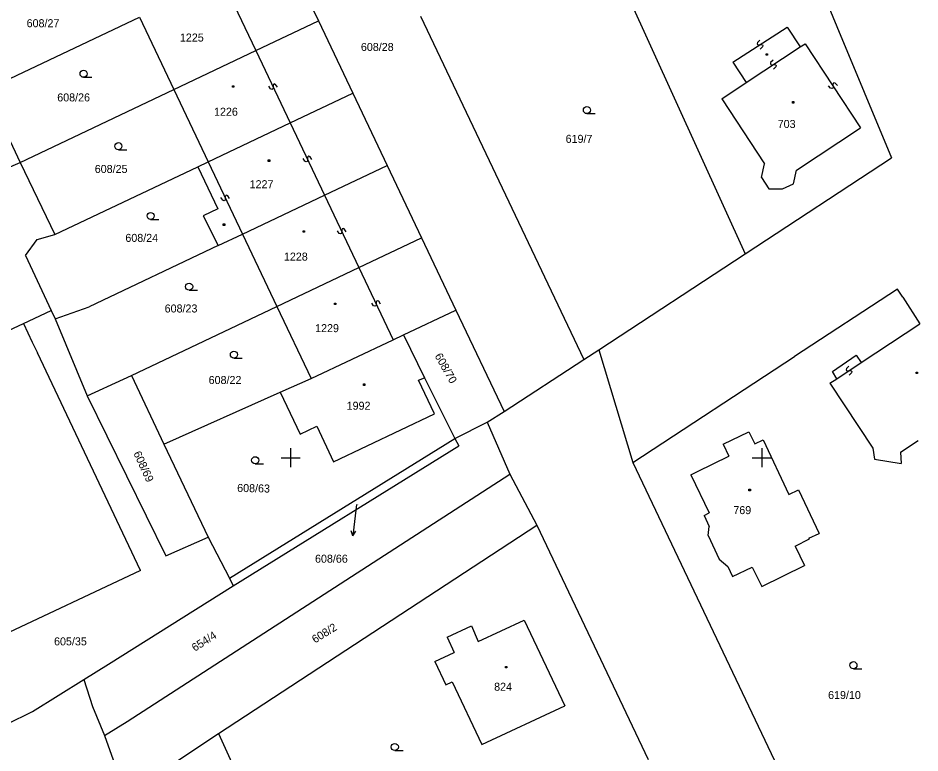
# Model space of a CAD drawing. Extents: x -493648 to -493033, y -1127718 to -1127026.
# Drawn here: x -493128.9 to -493033.2, y -1127181.4 to -1127103.3 of the extents above; entities that cross this region are included whole.
import ezdxf

# ---------------------------------------------------------------- set-up
doc = ezdxf.new("R2010")
doc.units = 0
doc.layers.add('katastrální mapa', color=7, linetype='Continuous')
doc.layers.add('síť', color=7, linetype='Continuous')

msp = doc.modelspace()

# ---------------------------------------------------------------- linework, layer by layer
at = {"layer": 'katastrální mapa'}
for p, q in [((-493067.27, -1127094.16), (-493051.77, -1127128.35)), ((-493100.69, -1127095.92), (-493097.05, -1127103.6)), ((-493045.2, -1127096.54), (-493042.01, -1127104.2)), ((-493107.33, -1127099.07), (-493103.69, -1127106.75)), ((-493132.35, -1127110.95), (-493116.05, -1127103.21)), ((-493116.05, -1127103.21), (-493112.4, -1127110.89)), ((-493086.2, -1127103.11), (-493068.87, -1127139.58)), ((-493103.69, -1127106.75), (-493097.05, -1127103.6)), ((-493097.05, -1127103.6), (-493093.4, -1127111.28)), ((-493042.01, -1127104.2), (-493036.22, -1127118.15)), ((-493053.06, -1127107.97), (-493047.3, -1127104.27)), ((-493047.3, -1127104.27), (-493045.91, -1127106.37)), ((-493050.45, -1127105.88), (-493050.48, -1127106.02)), ((-493050.48, -1127106.02), (-493050.43, -1127106.1)), ((-493050.19, -1127105.65), (-493050.45, -1127105.88)), ((-493050.43, -1127106.1), (-493050.29, -1127106.13)), ((-493050.29, -1127106.13), (-493050.07, -1127106.11)), ((-493050.07, -1127106.11), (-493049.93, -1127106.14)), ((-493049.93, -1127106.14), (-493049.88, -1127106.22)), ((-493045.91, -1127106.37), (-493045.39, -1127106.02)), ((-493045.39, -1127106.02), (-493039.5, -1127114.94)), ((-493112.4, -1127110.89), (-493103.69, -1127106.75)), ((-493103.69, -1127106.75), (-493100.04, -1127114.43)), ((-493051.63, -1127110.14), (-493045.91, -1127106.37)), ((-493049.91, -1127106.36), (-493050.17, -1127106.59)), ((-493049.88, -1127106.22), (-493049.91, -1127106.36)), ((-493049.53, -1127107.1), (-493049.38, -1127107.1)), ((-493049.53, -1127107.25), (-493049.53, -1127107.1)), ((-493049.38, -1127107.1), (-493049.38, -1127107.25)), ((-493053.06, -1127107.97), (-493051.63, -1127110.14)), ((-493049.38, -1127107.25), (-493049.53, -1127107.25)), ((-493049.05, -1127108.02), (-493049.07, -1127108.16)), ((-493048.78, -1127107.78), (-493049.05, -1127108.02)), ((-493049.07, -1127108.16), (-493049.02, -1127108.24)), ((-493049.02, -1127108.24), (-493048.88, -1127108.27)), ((-493048.88, -1127108.27), (-493048.66, -1127108.24)), ((-493048.49, -1127108.49), (-493048.76, -1127108.73)), ((-493048.66, -1127108.24), (-493048.52, -1127108.27)), ((-493048.52, -1127108.27), (-493048.47, -1127108.35)), ((-493048.47, -1127108.35), (-493048.49, -1127108.49)), ((-493121.98, -1127109.59), (-493121.1, -1127109.59)), ((-493128.69, -1127118.63), (-493112.4, -1127110.89)), ((-493112.4, -1127110.89), (-493108.76, -1127118.57)), ((-493106.17, -1127110.49), (-493106.02, -1127110.49)), ((-493106.17, -1127110.64), (-493106.17, -1127110.49)), ((-493106.02, -1127110.64), (-493106.17, -1127110.64)), ((-493106.02, -1127110.49), (-493106.02, -1127110.64)), ((-493102.14, -1127110.83), (-493102.33, -1127110.54)), ((-493102, -1127110.88), (-493102.14, -1127110.83)), ((-493101.91, -1127110.84), (-493102, -1127110.88)), ((-493101.87, -1127110.7), (-493101.91, -1127110.84)), ((-493101.86, -1127110.48), (-493101.87, -1127110.7)), ((-493101.82, -1127110.34), (-493101.86, -1127110.48)), ((-493101.73, -1127110.3), (-493101.82, -1127110.34)), ((-493101.59, -1127110.35), (-493101.73, -1127110.3)), ((-493101.4, -1127110.64), (-493101.59, -1127110.35)), ((-493054.24, -1127111.87), (-493051.63, -1127110.14)), ((-493042.68, -1127110.76), (-493042.92, -1127110.49)), ((-493042.54, -1127110.78), (-493042.68, -1127110.76)), ((-493042.46, -1127110.73), (-493042.54, -1127110.78)), ((-493042.43, -1127110.23), (-493042.46, -1127110.37)), ((-493042.46, -1127110.37), (-493042.43, -1127110.59)), ((-493042.43, -1127110.59), (-493042.46, -1127110.73)), ((-493042.35, -1127110.18), (-493042.43, -1127110.23)), ((-493042.21, -1127110.2), (-493042.35, -1127110.18)), ((-493041.97, -1127110.47), (-493042.21, -1127110.2)), ((-493132.35, -1127110.95), (-493128.69, -1127118.63)), ((-493100.04, -1127114.43), (-493093.4, -1127111.28)), ((-493093.4, -1127111.28), (-493089.75, -1127118.95)), ((-493054.24, -1127111.87), (-493049.69, -1127118.77)), ((-493046.72, -1127112.17), (-493046.57, -1127112.17)), ((-493046.72, -1127112.32), (-493046.72, -1127112.17)), ((-493046.57, -1127112.32), (-493046.72, -1127112.32)), ((-493046.57, -1127112.17), (-493046.57, -1127112.32)), ((-493068.55, -1127113.45), (-493067.67, -1127113.45)), ((-493108.76, -1127118.57), (-493100.04, -1127114.43)), ((-493100.04, -1127114.43), (-493096.39, -1127122.11)), ((-493046.32, -1127119.47), (-493039.5, -1127114.94)), ((-493118.28, -1127117.28), (-493117.4, -1127117.28)), ((-493109.86, -1127119.09), (-493108.76, -1127118.57)), ((-493108.76, -1127118.57), (-493105.11, -1127126.25)), ((-493102.37, -1127118.37), (-493102.22, -1127118.37)), ((-493102.37, -1127118.52), (-493102.37, -1127118.37)), ((-493102.22, -1127118.52), (-493102.37, -1127118.52)), ((-493102.22, -1127118.37), (-493102.22, -1127118.52)), ((-493098.49, -1127118.51), (-493098.68, -1127118.22)), ((-493098.35, -1127118.56), (-493098.49, -1127118.51)), ((-493098.26, -1127118.52), (-493098.35, -1127118.56)), ((-493098.22, -1127118.38), (-493098.26, -1127118.52)), ((-493098.21, -1127118.16), (-493098.22, -1127118.38)), ((-493098.17, -1127118.02), (-493098.21, -1127118.16)), ((-493098.08, -1127117.98), (-493098.17, -1127118.02)), ((-493097.94, -1127118.03), (-493098.08, -1127117.98)), ((-493097.75, -1127118.32), (-493097.94, -1127118.03)), ((-493051.77, -1127128.35), (-493036.22, -1127118.15)), ((-493130.25, -1127119.31), (-493128.69, -1127118.63)), ((-493128.69, -1127118.63), (-493125.04, -1127126.3)), ((-493125.04, -1127126.3), (-493109.86, -1127119.09)), ((-493109.86, -1127119.09), (-493107.74, -1127123.56)), ((-493096.39, -1127122.11), (-493089.75, -1127118.95)), ((-493089.75, -1127118.95), (-493086.11, -1127126.63)), ((-493050.03, -1127120.23), (-493049.69, -1127118.77)), ((-493046.64, -1127120.91), (-493046.32, -1127119.47)), ((-493050.03, -1127120.23), (-493049.24, -1127121.43)), ((-493049.24, -1127121.43), (-493047.8, -1127121.43)), ((-493047.8, -1127121.43), (-493046.64, -1127120.91)), ((-493107.21, -1127122.65), (-493107.4, -1127122.36)), ((-493106.93, -1127122.3), (-493106.94, -1127122.52)), ((-493106.89, -1127122.16), (-493106.93, -1127122.3)), ((-493106.8, -1127122.12), (-493106.89, -1127122.16)), ((-493106.66, -1127122.17), (-493106.8, -1127122.12)), ((-493106.47, -1127122.46), (-493106.66, -1127122.17)), ((-493105.11, -1127126.25), (-493096.39, -1127122.11)), ((-493096.39, -1127122.11), (-493092.75, -1127129.78)), ((-493107.07, -1127122.7), (-493107.21, -1127122.65)), ((-493106.98, -1127122.66), (-493107.07, -1127122.7)), ((-493106.94, -1127122.52), (-493106.98, -1127122.66)), ((-493107.74, -1127123.56), (-493109.3, -1127124.3)), ((-493109.3, -1127124.3), (-493107.68, -1127127.47)), ((-493114.86, -1127124.69), (-493113.98, -1127124.69)), ((-493107.15, -1127125.17), (-493107, -1127125.17)), ((-493107.15, -1127125.32), (-493107.15, -1127125.17)), ((-493107, -1127125.17), (-493107, -1127125.32)), ((-493107.68, -1127127.47), (-493105.11, -1127126.25)), ((-493107, -1127125.32), (-493107.15, -1127125.32)), ((-493105.11, -1127126.25), (-493101.47, -1127133.92)), ((-493098.66, -1127125.88), (-493098.51, -1127125.88)), ((-493098.66, -1127126.03), (-493098.66, -1127125.88)), ((-493098.51, -1127126.03), (-493098.66, -1127126.03)), ((-493098.51, -1127125.88), (-493098.51, -1127126.03)), ((-493094.84, -1127126.19), (-493095.04, -1127125.89)), ((-493094.71, -1127126.23), (-493094.84, -1127126.19)), ((-493094.62, -1127126.19), (-493094.71, -1127126.23)), ((-493094.57, -1127126.06), (-493094.62, -1127126.19)), ((-493094.52, -1127125.7), (-493094.57, -1127125.83)), ((-493094.57, -1127125.83), (-493094.57, -1127126.06)), ((-493094.43, -1127125.66), (-493094.52, -1127125.7)), ((-493094.3, -1127125.7), (-493094.43, -1127125.66)), ((-493094.1, -1127126), (-493094.3, -1127125.7)), ((-493128.13, -1127128.52), (-493126.91, -1127126.81)), ((-493126.91, -1127126.81), (-493125.04, -1127126.3)), ((-493092.75, -1127129.78), (-493086.11, -1127126.63)), ((-493086.11, -1127126.63), (-493082.46, -1127134.31)), ((-493107.68, -1127127.47), (-493121.38, -1127133.98)), ((-493128.13, -1127128.52), (-493125.41, -1127134.36)), ((-493067.3, -1127138.55), (-493051.77, -1127128.35)), ((-493101.47, -1127133.92), (-493092.75, -1127129.78)), ((-493092.75, -1127129.78), (-493089.1, -1127137.46)), ((-493110.77, -1127132.2), (-493109.89, -1127132.2)), ((-493035.59, -1127132.09), (-493046.51, -1127139.25)), ((-493035.02, -1127132.96), (-493035.59, -1127132.09)), ((-493095.34, -1127133.57), (-493095.19, -1127133.57)), ((-493095.34, -1127133.72), (-493095.34, -1127133.57)), ((-493095.19, -1127133.72), (-493095.34, -1127133.72)), ((-493095.19, -1127133.57), (-493095.19, -1127133.72)), ((-493091.2, -1127133.86), (-493091.39, -1127133.57)), ((-493091.06, -1127133.91), (-493091.2, -1127133.86)), ((-493090.97, -1127133.87), (-493091.06, -1127133.91)), ((-493090.93, -1127133.73), (-493090.97, -1127133.87)), ((-493090.92, -1127133.51), (-493090.93, -1127133.73)), ((-493090.88, -1127133.37), (-493090.92, -1127133.51)), ((-493090.79, -1127133.33), (-493090.88, -1127133.37)), ((-493090.65, -1127133.38), (-493090.79, -1127133.33)), ((-493090.46, -1127133.67), (-493090.65, -1127133.38)), ((-493035.02, -1127132.96), (-493033.2, -1127135.76)), ((-493128.35, -1127135.75), (-493125.41, -1127134.36)), ((-493125.41, -1127134.36), (-493125, -1127135.23)), ((-493125, -1127135.23), (-493121.38, -1127133.98)), ((-493116.9, -1127141.26), (-493101.47, -1127133.92)), ((-493101.47, -1127133.92), (-493097.82, -1127141.6)), ((-493088.02, -1127136.95), (-493082.46, -1127134.31)), ((-493082.46, -1127134.31), (-493077.35, -1127145.08)), ((-493130.46, -1127136.74), (-493128.35, -1127135.75)), ((-493128.35, -1127135.75), (-493127.42, -1127137.73)), ((-493125, -1127135.23), (-493121.58, -1127143.43)), ((-493039.44, -1127139.89), (-493033.2, -1127135.76)), ((-493127.42, -1127137.73), (-493126.88, -1127138.86)), ((-493097.82, -1127141.6), (-493089.1, -1127137.46)), ((-493089.1, -1127137.46), (-493088.02, -1127136.95)), ((-493088.02, -1127136.95), (-493085.79, -1127141.51)), ((-493068.87, -1127139.58), (-493067.3, -1127138.55)), ((-493067.3, -1127138.55), (-493063.68, -1127150.51)), ((-493115.95, -1127161.97), (-493126.88, -1127138.86)), ((-493106.02, -1127139.42), (-493105.14, -1127139.42)), ((-493077.35, -1127145.08), (-493068.87, -1127139.58)), ((-493063.68, -1127150.51), (-493046.51, -1127139.25)), ((-493042.5, -1127140.85), (-493039.96, -1127139.12)), ((-493039.96, -1127139.12), (-493039.44, -1127139.89)), ((-493042.03, -1127141.61), (-493039.44, -1127139.89)), ((-493041.01, -1127140.51), (-493041.04, -1127140.65)), ((-493040.75, -1127140.28), (-493041.01, -1127140.51)), ((-493117.73, -1127141.65), (-493116.9, -1127141.26)), ((-493116.9, -1127141.26), (-493113.44, -1127148.57)), ((-493085.79, -1127141.51), (-493082.56, -1127147.94)), ((-493042.03, -1127141.61), (-493042.5, -1127140.85)), ((-493041.04, -1127140.65), (-493040.98, -1127140.74)), ((-493040.98, -1127140.74), (-493040.85, -1127140.76)), ((-493040.85, -1127140.76), (-493040.62, -1127140.74)), ((-493040.46, -1127140.99), (-493040.72, -1127141.22)), ((-493040.62, -1127140.74), (-493040.49, -1127140.76)), ((-493040.49, -1127140.76), (-493040.43, -1127140.85)), ((-493040.43, -1127140.85), (-493040.46, -1127140.99)), ((-493033.6, -1127140.9), (-493033.45, -1127140.9)), ((-493033.6, -1127141.05), (-493033.6, -1127140.9)), ((-493033.45, -1127141.05), (-493033.6, -1127141.05)), ((-493033.45, -1127140.9), (-493033.45, -1127141.05)), ((-493121.58, -1127143.43), (-493117.73, -1127141.65)), ((-493101.11, -1127143.03), (-493097.82, -1127141.6)), ((-493092.27, -1127142.16), (-493092.12, -1127142.16)), ((-493092.27, -1127142.31), (-493092.27, -1127142.16)), ((-493092.12, -1127142.31), (-493092.27, -1127142.31)), ((-493092.12, -1127142.16), (-493092.12, -1127142.31)), ((-493042.76, -1127142.09), (-493042.03, -1127141.61)), ((-493042.76, -1127142.09), (-493038.2, -1127148.97)), ((-493121.58, -1127143.43), (-493113.24, -1127160.42)), ((-493113.44, -1127148.57), (-493101.11, -1127143.03)), ((-493079.13, -1127146.23), (-493077.35, -1127145.08)), ((-493082.56, -1127147.94), (-493079.13, -1127146.23)), ((-493079.13, -1127146.23), (-493076.73, -1127151.76)), ((-493054.1, -1127148.57), (-493051.35, -1127147.24)), ((-493051.35, -1127147.24), (-493050.73, -1127148.51)), ((-493106.5, -1127162.8), (-493082.56, -1127147.94)), ((-493082.56, -1127147.94), (-493082.16, -1127148.75)), ((-493050.73, -1127148.51), (-493049.83, -1127148.09)), ((-493049.83, -1127148.09), (-493047.13, -1127153.9)), ((-493035.25, -1127149.39), (-493033.38, -1127148.17)), ((-493113.44, -1127148.57), (-493108.75, -1127158.45)), ((-493106.09, -1127163.6), (-493082.16, -1127148.75)), ((-493054.1, -1127148.57), (-493053.48, -1127149.85)), ((-493038.2, -1127148.97), (-493038.02, -1127150.15)), ((-493038.02, -1127150.15), (-493035.21, -1127150.61)), ((-493035.25, -1127149.39), (-493035.21, -1127150.61)), ((-493103.76, -1127150.64), (-493102.88, -1127150.64)), ((-493063.68, -1127150.51), (-493043.37, -1127193.26)), ((-493117.34, -1127178.03), (-493076.73, -1127151.76)), ((-493076.73, -1127151.76), (-493073.86, -1127157.16)), ((-493057.53, -1127151.81), (-493055.57, -1127155.86)), ((-493051.35, -1127153.35), (-493051.2, -1127153.35)), ((-493051.35, -1127153.5), (-493051.35, -1127153.35)), ((-493051.2, -1127153.5), (-493051.35, -1127153.5)), ((-493051.2, -1127153.35), (-493051.2, -1127153.5)), ((-493047.13, -1127153.9), (-493046.09, -1127153.41)), ((-493046.09, -1127153.41), (-493043.89, -1127158.04)), ((-493093.01, -1127154.96), (-493093.22, -1127156.79)), ((-493056.11, -1127156.12), (-493055.57, -1127155.86)), ((-493093.22, -1127156.79), (-493093.39, -1127158.28)), ((-493056.11, -1127156.12), (-493055.56, -1127157.3)), ((-493107.66, -1127179.29), (-493073.86, -1127157.16)), ((-493093.39, -1127158.28), (-493093.58, -1127157.76)), ((-493093.39, -1127158.28), (-493093.09, -1127157.81)), ((-493073.86, -1127157.16), (-493062.04, -1127182.05)), ((-493055.67, -1127158.26), (-493055.56, -1127157.3)), ((-493113.24, -1127160.42), (-493108.75, -1127158.45)), ((-493108.75, -1127158.45), (-493106.5, -1127162.8)), ((-493055.67, -1127158.26), (-493054.51, -1127160.76)), ((-493046.46, -1127159.38), (-493044.94, -1127158.63)), ((-493044.98, -1127158.54), (-493043.89, -1127158.04)), ((-493044.98, -1127158.54), (-493044.94, -1127158.63)), ((-493046.46, -1127159.38), (-493045.45, -1127161.45)), ((-493054.51, -1127160.76), (-493053.59, -1127161.54)), ((-493053.59, -1127161.54), (-493053.09, -1127162.63)), ((-493053.09, -1127162.63), (-493051, -1127161.61)), ((-493051, -1127161.61), (-493049.98, -1127163.67)), ((-493049.98, -1127163.67), (-493045.45, -1127161.45)), ((-493115.95, -1127161.97), (-493133.58, -1127170.28)), ((-493106.5, -1127162.8), (-493106.09, -1127163.6)), ((-493119.32, -1127171.94), (-493106.09, -1127163.6)), ((-493080.09, -1127169.51), (-493075.21, -1127167.24)), ((-493075.21, -1127167.24), (-493070.9, -1127176.36)), ((-493083.39, -1127169.07), (-493080.81, -1127167.86)), ((-493080.81, -1127167.86), (-493080.09, -1127169.51)), ((-493083.39, -1127169.07), (-493082.63, -1127170.67)), ((-493084.68, -1127171.63), (-493082.63, -1127170.67)), ((-493121.95, -1127173.57), (-493119.32, -1127171.94)), ((-493084.68, -1127171.63), (-493083.52, -1127174.12)), ((-493077.2, -1127172.18), (-493077.05, -1127172.18)), ((-493077.2, -1127172.33), (-493077.2, -1127172.18)), ((-493077.05, -1127172.18), (-493077.05, -1127172.33)), ((-493077.05, -1127172.33), (-493077.2, -1127172.33)), ((-493040.26, -1127172.41), (-493039.38, -1127172.41)), ((-493127.41, -1127176.97), (-493121.95, -1127173.57)), ((-493121.95, -1127173.57), (-493121.04, -1127176.44)), ((-493083.52, -1127174.12), (-493082.84, -1127173.8)), ((-493082.84, -1127173.8), (-493079.72, -1127180.47)), ((-493130.11, -1127178.29), (-493127.41, -1127176.97)), ((-493121.04, -1127176.44), (-493119.75, -1127179.52)), ((-493079.72, -1127180.47), (-493070.9, -1127176.36)), ((-493119.75, -1127179.52), (-493117.34, -1127178.03)), ((-493119.75, -1127179.52), (-493117.52, -1127185.82)), ((-493117.52, -1127185.82), (-493107.66, -1127179.29)), ((-493107.66, -1127179.29), (-493098.45, -1127199.56)), ((-493088.94, -1127181.1), (-493088.06, -1127181.1))]:
    msp.add_line(p, q, dxfattribs=at)
for points in [[(-493101.11, -1127143.03), (-493098.99, -1127147.5), (-493097.23, -1127146.66), (-493095.44, -1127150.42), (-493084.72, -1127145.35), (-493086.42, -1127141.77), (-493085.79, -1127141.51)], [(-493057.53, -1127151.81), (-493056.81, -1127151.46), (-493053.48, -1127149.85)]]:
    msp.add_lwpolyline(points, dxfattribs=at)
for centre in [(-493121.98, -1127109.215), (-493068.55, -1127113.075), (-493118.28, -1127116.905), (-493114.86, -1127124.315), (-493110.77, -1127131.825), (-493106.02, -1127139.045), (-493103.76, -1127150.265), (-493040.26, -1127172.035), (-493088.94, -1127180.725)]:
    msp.add_circle(centre, 0.375, dxfattribs=at)
at = {"layer": 'síť'}
for p, q in [((-493100, -1127149), (-493100, -1127151)), ((-493050, -1127149), (-493050, -1127151)), ((-493101, -1127150), (-493099, -1127150)), ((-493051, -1127150), (-493049, -1127150))]:
    msp.add_line(p, q, dxfattribs=at)

# ---------------------------------------------------------------- texts
at = {"layer": 'katastrální mapa'}
for s, height, p in [('608/27', 0.849996, (-493128.02, -1127104.27)), ('1225', 0.849996, (-493111.75, -1127105.79)), ('608/28', 0.849996, (-493092.54, -1127106.79)), ('608/26', 0.849996, (-493124.77, -1127112.15)), ('1226', 0.849996, (-493108.13, -1127113.67)), ('703', 0.849996, (-493048.3, -1127114.97)), ('619/7', 0.849996, (-493070.81, -1127116.55)), ('608/25', 0.849996, (-493120.79, -1127119.75)), ('1227', 0.849996, (-493104.35, -1127121.37)), ('608/24', 0.849996, (-493117.54, -1127127.07)), ('1228', 0.849996, (-493100.71, -1127129.06)), ('608/23', 0.849996, (-493113.37, -1127134.57)), ('1229', 0.849996, (-493097.4, -1127136.66)), ('608/22', 0.849996, (-493108.7, -1127142.17)), ('1992', 0.849996, (-493094.05, -1127144.9)), ('608/66', 0.049998, (-493093.01, -1127154.96)), ('769', 0.849996, (-493053.01, -1127155.99)), ('608/66', 0.849996, (-493097.41, -1127161.15)), ('605/35', 0.849996, (-493125.11, -1127169.93)), ('824', 0.849996, (-493078.4, -1127174.75)), ('619/10', 0.849996, (-493042.95, -1127175.63))]:
    msp.add_text(s, height=height, dxfattribs=at).set_placement(p)
for s, rotation, p in [('608/70', 299.43, (-493084.74, -1127139.18)), ('608/69', 294.732, (-493116.71, -1127149.53)), ('608/63', 358.8389972, (-493105.68, -1127153.63)), ('608/2', 31.914, (-493097.41, -1127169.74)), ('654/4', 32.5979972, (-493110.16, -1127170.62))]:
    msp.add_text(s, height=0.849996, rotation=rotation, dxfattribs=at).set_placement(p)

doc.saveas('drawing.dxf')
